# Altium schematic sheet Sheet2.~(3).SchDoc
size A4
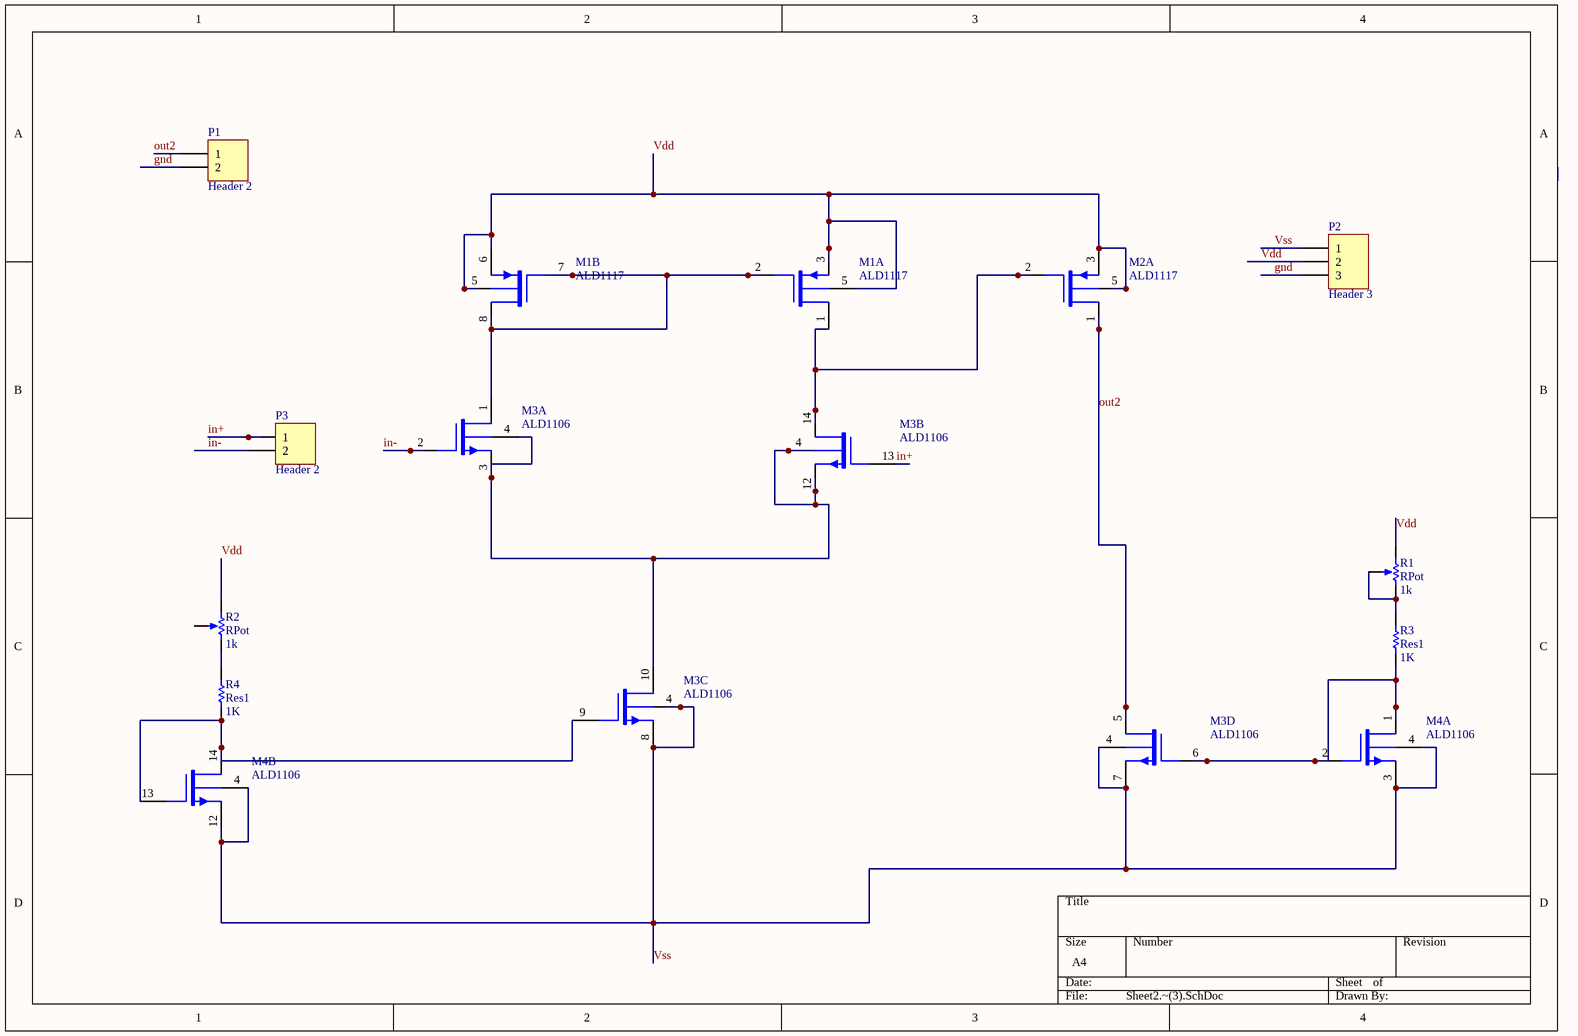
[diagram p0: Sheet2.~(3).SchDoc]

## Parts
M1  ALD1117  [DIP-8]  (parts A,B of 2)
M2  ALD1117  [DIP-8]  (part A of 2)
M3  ALD1106  [DIP-14]  (parts A,B,C,D of 4)
M4  ALD1106  [DIP-14]  (parts A,B of 4)
P1  Header 2  [HDR1X2]
P2  Header 3  [HDR1X3]
P3  Header 2  [HDR1X2]
R1  RPot  value 1k  [VR5]
R2  RPot  value 1k  [VR5]
R3  Res1  value 1K  [AXIAL-0.3]
R4  Res1  value 1K  [AXIAL-0.3]

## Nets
gnd: P1.2 P2.3
in+: M3.13(GN2) P3.1
in-: M3.2(GN1) P3.2
out2: M2.1(DP1) M3.5(DN4) P1.1
Vdd: M1.3(SP1) M1.5(V+) M1.6(SP2) M2.3(SP1) M2.5(V+) P2.2 R1.1(TOP) R2.1(TOP)
Vss: M3.4(V-) M3.7(SN4) M3.8(SN3) M4.3(SN1) M4.4(V-) M4.12(SN2) P2.1
NetM1_1: M1.1(DP1) M2.2(GP1) M3.14(DN2)
NetM1_2: M1.2(GP1) M1.7(GP2) M1.8(DP2) M3.1(DN1)
NetM3_3: M3.3(SN1) M3.4(V-) M3.10(DN3) M3.12(SN2)
NetM3_6: M3.6(GN4) M4.1(DN1) M4.2(GN1) R3.2
NetM3_9: M3.9(GN3) M4.13(GN2) M4.14(DN2) R4.2
NetR1_2: R1.2(TAP) R1.3(BOT) R3.1
NetR2_3: R2.3(BOT) R4.1

Not connected (* = marked no-connect by the designer): R2 2(TAP)

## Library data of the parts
M1 M2 = ALD1117: Dual P-channel matched MOSFET array
M3 M4 = ALD1106: Quad N-channel matched MOSFET array
P1 P3 = Header 2: Header, 2-Pin
P2 = Header 3: Header, 3-Pin
R1 R2 = RPot: Potentiometer; Sim Note: Enter the Resistance value and the set point into parameter fields.; Set Position: 0.5
R3 R4 = Res1: Resistor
